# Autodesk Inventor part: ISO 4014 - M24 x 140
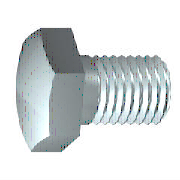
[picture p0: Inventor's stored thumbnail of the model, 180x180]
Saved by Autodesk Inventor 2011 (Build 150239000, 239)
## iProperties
Created: 2009-02
Part Number: ISO 4014 - M24 x 140
Material: Stainless Steel, 440C
Description: Hexagon head bolt - product grades A and B
Document SubType Name: Modeling
Standard: ISO 4014
Designer: V.de Jong
Standard Revision: Third edition 1999-09-01
Standards Organization: ISO
Language: en-US
Size Designation: M24 x 140
Categories: <MemberInstance><Categories><Category DisplayName="Fasteners" InternalName="e4da775c-781d-43d5-af7c-5136215cf5a6" Mnemonic="FSTN"><Category DisplayName="Bolts"
Density: 7.75 g/cm^3
Mass: 618.529 g
Surface Area: 145.175 cm^2
Volume: 79.8102 cm^3
IsCustomPart: 0
Author: V.de Jong
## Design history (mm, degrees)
body "Solid1"
workplane "Work Plane1"
revolve "Body" stored, may be unused: angle "d12" = 90 deg
sketch "Sketch2"
  geometry: L1 (0, 20.785)-(18, 10.392); L2 (18, 10.392)-(18, -10.392); L3 (18, -10.392)-(0, -20.785); L4 (0, -20.785)-(-18, -10.392); L5 (-18, -10.392)-(-18, 10.392); L6 (-18, 10.392)-(0, 20.785); 2 further points
  constraints: 12 end point, 1 coincident, 1 vertical, 11 other
  dimensions: "d11" = 36 distance between parallel lines of L5 L2 (= SW)
extrude "Head" join sketch "Sketch2" distance "d3" = 14.2 (= KOH - SD); taper "d4" = 0 deg
revolve "Chamfer1" stored, may be unused: angle "d21" = 90 deg
feature "Thread" dims "d15" = 60 (= GEL), "d16" = 0
chamfer "Chamfer2" distance "d6" = 1.84035 (= -0.5 x SPD + 0.5 x GD); stored, may be unused: second distance "d7" = 1.84045 (computed from GUL), angle "d55" = 45 deg
sketch "Sketch1"
  geometry: L1 (0, 16.805)-(0, 12); L2 (80, 12)-(140, 12); L3 (140, 12)-(140, 0); L4 (140, 0)-(-0.8, 0); L5 (-28.96, 0)-(168.16, 0) reference; L6 (-0.8, 0)-(-0.8, 16.805); L7 (-0.8, 16.805)-(0, 16.805); L8 (80, 12)-(78.16, 12); L9 (78.16, 12)-(0, 12); L10 (0, -3.361)-(0, 20.166) reference
  constraints: 16 end point, 2 collinear, 2 perpendicular, 1 parallel
  dimensions: "d0" = 140 distance between parallel lines of L3 L1 (= NLG); "d1" = 60 distance from line of L2.start L3 (= GEL); "d2" = 24 diameter of L2 L4 (= GD); "d9" = 0.8001 distance between parallel lines of L6 L1 (computed from SD); "d10" = 33.61 diameter of L7 L4 (= SD2); "d13" = 1.84045 distance of L2.start L8.end (computed from GAL); "d14" = 24 diameter of L9 L4 (= BDM)
sketch "Sketch4"
  geometry: L1 (-15, 18)-(-15, 20.785); L2 (-15, 20.785)-(-13.392, 20.785); L3 (-13.392, 20.785)-(-15, 18); L4 (-17.84, 0)-(2.04, 0) reference; L5 (-0.8, 20.785)-(-15, 20.785) reference; L6 (-15, 10.392)-(-15, 20.785) reference
  constraints: 6 end point, 2 collinear, 1 perpendicular, 1 vertical
  dimensions: "d5" = 30 deg angle of L3 L1 (= ANG1); "d19" = 36 diameter of L1.start L4 (= SW0)
other parameters: "NLG" = 140 [user parameter; used in 1 equation term], "GD" = 24 (= NND) [user parameter; used in 2 equation terms], "BDM" = 24 (= NND) [user parameter; used in 1 equation term], "KOH" = 15 [user parameter; used in 1 equation term], "GEL" = 60 [user parameter; used in 2 equation terms], "SW" = 36 [user parameter; used in 3 equation terms], "SW0" = 36 (= SW) [user parameter; used in 1 equation term], "SPD" = 20.3193 (= NND - 1.2269 x PTC) [user parameter; used in 1 equation term], "SD2" = 33.61 [user parameter; used in 2 equation terms], "SD" = 0.8 [user parameter; used in 2 equation terms], "ANG1" = 30 deg [user parameter; used in 1 equation term], "GAL" = 1.84035 (= 0.61345 x PTC) [user parameter; used in 1 equation term], "GUL" = 1.84035 (= 0.61345 x PTC) [user parameter; used in 1 equation term], "d8" = 0, "RR" = 0.8 [user parameter], "d57" = 0, "d58" = 0, "TPU" = 3.33333 (computed from PTC) [user parameter], "GD1" = 20.3193 (= THREADDIA - 1.2269 x PTC) [user parameter], "THREADDIA" = 24 [user parameter; used in 1 equation term], "SDH" = 33.61 (= SD2) [user parameter], "TOA" = 30 deg [user parameter], "PTC" = 3 [user parameter; used in 5 equation terms], "NND" = 24 [user parameter; used in 3 equation terms], "E0" = 41.58 (= 1.155 x SW) [user parameter]
